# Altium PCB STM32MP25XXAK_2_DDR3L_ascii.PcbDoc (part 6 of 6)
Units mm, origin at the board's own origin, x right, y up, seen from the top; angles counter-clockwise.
Board outline 120 x 79.6 mm, 4 copper layers (Top Layer, Signal Layer 1, Signal Layer 2, Bottom Layer), stack 1.614 mm thick; 247 components, 155 nets, 1312 pads, 792 vias.
Unrouted connection lines stored in the file: 6.
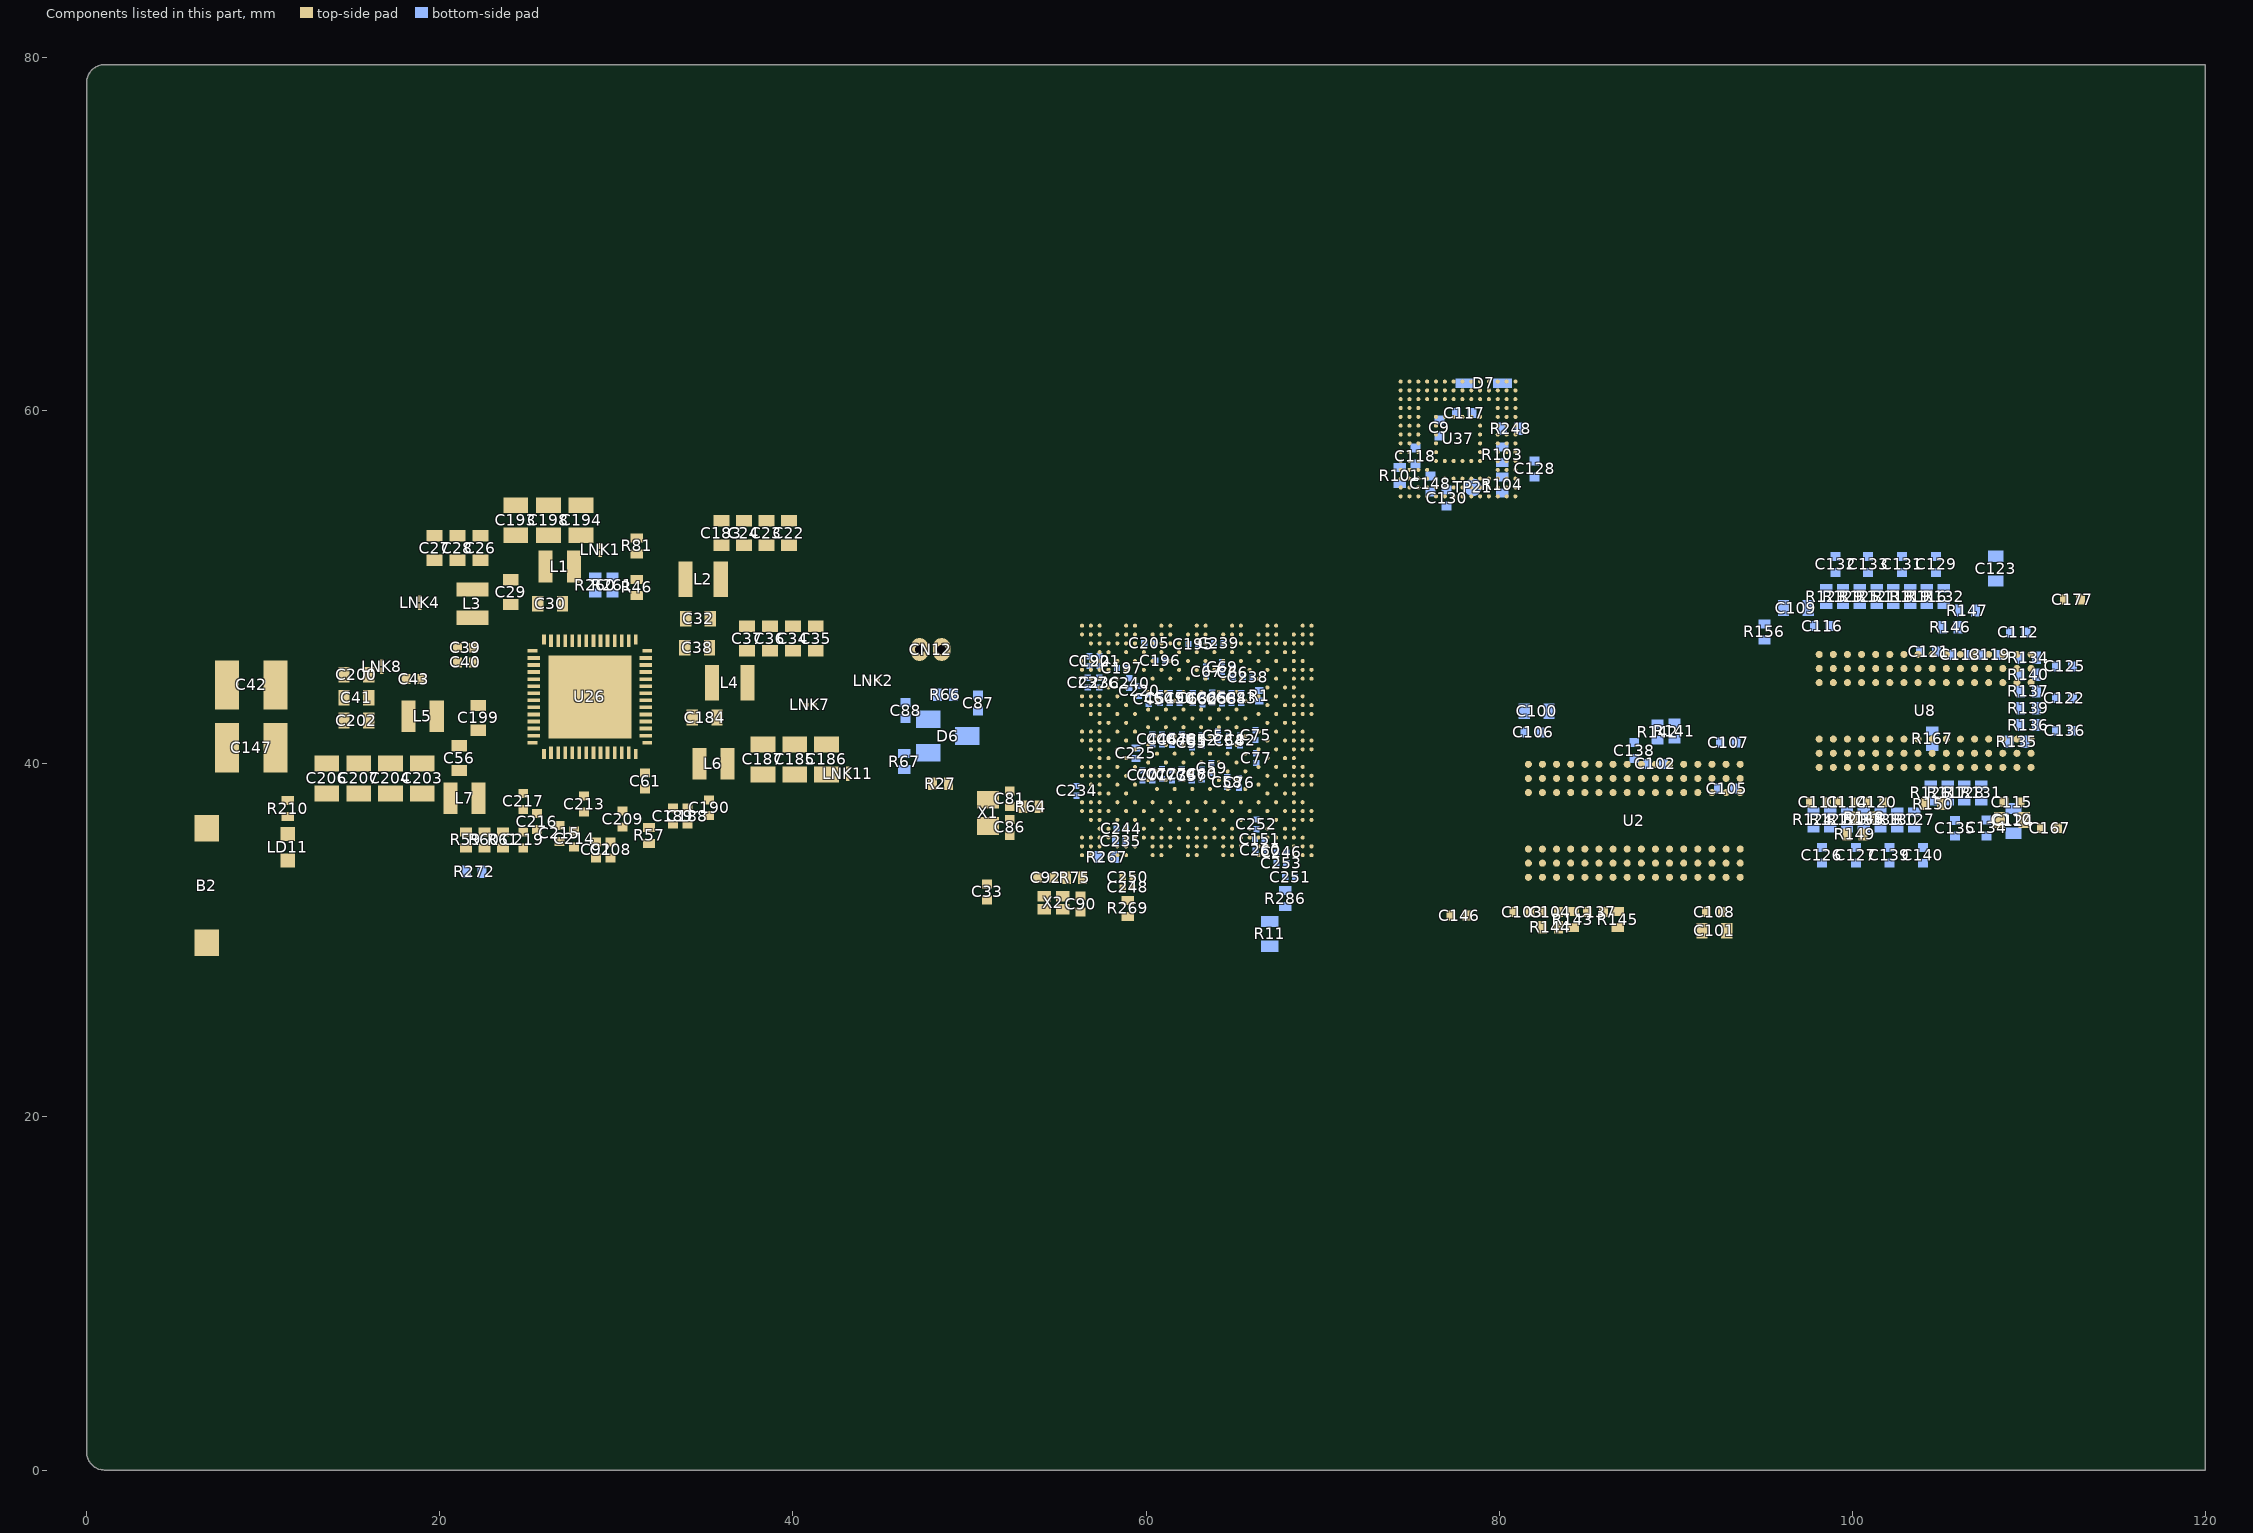
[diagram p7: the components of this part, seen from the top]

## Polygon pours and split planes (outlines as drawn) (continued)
1V8 on Signal Layer 2 "1V8_L03_P052" (solid, pour order 52): 29.175,64.6 29.175,61.472 70.193,61.472 70.252,51.21 84.26,51.21 86.225,53.175 86.225,64.6
GND on Top Layer "GND_L01_P053" (solid, remove dead copper, pour order 53): 0,79.797 119.996,79.797 119.996,0.197 0,0.197
5V_STLK on Top Layer "5V_VIN" (solid, pour order 17): 22.51,43.62 23.167,43.62 23.35,43.803 23.35,43.463 22.867,42.98 22.51,42.98
VDDCPU on Top Layer "I_SENS_VDDCPU_P" (solid, pour order 18): 17.812,51.845 17.812,49.998 18.335,49.475 22.75,49.475 22.745,49.48 22.745,51.845
VDDCORE on Top Layer "I_SENS_VDDCORE_P" (solid, pour order 19): 41.007,52.695 43.889,49.813 43.889,43.586 43.894,43.581 42.44,43.581 41.895,44.126 41.895,48.827 41.522,49.2 39.875,49.2 35.515,49.2 35.505,52.695
VDDGPU on Top Layer "I_SENS_VDDGPU_P" (solid, pour order 20): 41.603,43.6 41.745,43.742 41.745,46.72 37.025,46.72 37.025,43.6
VDDIO on Top Layer "VDDIO" (solid, pour order 22): 30.995,46.77 30.995,48.568 31.53,49.103 31.712,49.103 32.15,48.664 32.15,48.123 31.45,47.423 31.45,46.77
3V3 on Top Layer "3V3" (solid, pour order 23): 12.887,36.548 13.062,36.373 19.41,36.373 20.712,37.675 20.712,38.523 13.088,38.523 12.887,38.323
NetL6_1 on Top Layer "NetL13_1" (solid, pour order 25): 33.375,41.863 33.838,41.4 35.1,41.4 35.1,39.1 35.098,39.098 33.801,39.098 33.801,40.722 33.375,41.148
GND on Bottom Layer "GND_L04_P055" (solid, remove dead copper, pour order 55): 0,79.6 120,79.6 120,0 0,0
VTT_DDR on Bottom Layer "VTT" (solid, pour order 39): 104.31,35.002 105.908,36.6 109.033,36.6 111.658,39.225 111.658,49.075 109.583,51.15 98.183,51.15 98.183,49.627 108.079,49.627 109.983,47.724 109.983,41.223 106.96,38.2 103.996,38.2 103.996,36.702 97.158,36.702 97.158,35
GND on Signal Layer 1 "GND_L02_P000" (solid, remove dead copper, pour order 0): 0,79.6 120,79.6 120,0 0,0

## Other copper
Top Layer:
  rectangle net VDD_DDR: 15.655,41.8 18.625,43.6

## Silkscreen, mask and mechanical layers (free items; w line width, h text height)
Top Overlay:
  text "J" at 27.263,70.56 h15
Drill Drawing:
  drawing of 194 lines, arcs and shapes, not listed
  text "PCB SPECIFICATIONS :" at -27.02,127.275 h3
  text "A.   MATERIAL :" at -27.02,123.275 h3
  text "FR-4" at 11.48,123.275 h3
  text "TG-170" at 27.98,123.275 h3
  text "X  TG-150" at 46.23,123.275 h3
  text "TG-140" at 62.23,123.275 h3
  text "B.   MATERIAL FAMILY :" at -27.02,120.275 h3
  text "N/A" at 11.48,120.275 h3
  text "C.   SOLDERMASK COLOR :" at -27.02,117.275 h3
  text "GREEN" at 11.48,117.275 h3
  text "X  BLUE" at 27.98,117.275 h3
  text "RED" at 46.23,117.275 h3
  text "BLACK" at 62.23,117.275 h3
  text "D.   SILKSCREEN COLOR :" at -27.02,114.275 h3
  text "X  WHITE" at 11.48,114.275 h3
  text "YELLOW" at 27.98,114.275 h3
  text "BLACK" at 46.23,114.275 h3
  text "PCB : TYPE 4" at 187.138,113.471 h3
  text "Layer" at 122.2,111.475 h2
  text "Name" at 130.564,111.475 h2
  text "Material" at 146.732,111.475 h2
  text "Thickness" at 161.266,111.475 h2
  text "Constant" at 173.202,111.475 h2
  text "E.   SURFACE FINISH :" at -27.02,111.275 h3
  text "X  ENIG" at 11.48,111.275 h3
  text "IMMERSION SILVER" at 27.98,111.275 h3
  text "IMMERSION TIN" at 62.23,111.275 h3
  text "HASL" at 11.48,108.275 h3
  text "HASL (PB-FREE)" at 27.98,108.275 h3
  text "GOLDEN FINGER" at 62.23,108.275 h3
  text "ASPECT-RATIO, AXE Z :" at 187.138,107.971 h3
  text "Top Overlay" at 130.564,107.475 h2
  text "F.   IMPEDANCE CONTROL :" at -27.02,105.275 h3
  text "NO" at 11.48,105.275 h3
  text "X  YES" at 27.98,105.275 h3
  text "Top Solder" at 130.564,103.475 h2
  text "Solder Resist" at 146.732,103.475 h2
  text "0.025mm" at 161.266,103.475 h2
  text "3.5" at 173.202,103.475 h2
  text "G.   THROUGH VIA :" at -27.02,102.275 h3
  text "PLUG THE VIAS WHICH ARE COVERED WITH SOLDERMASK ONE OR TWO SIDE." at 11.48,102.275 h3
  text "6 :1  to  8 :1 / LEVEL \"B\"" at 187.157,101.224 h3
  text "1" at 122.2,99.475 h2
  text "Top Layer" at 130.564,99.475 h2
  text "0.037mm" at 161.266,99.475 h2
  text "PLUG MATERIAL :" at 11.48,99.275 h3
  text "X  SOLDERMASK" at 36.98,99.275 h3
  text "NON-CONDUCTIVE EPOXY." at 62.23,99.275 h3
  text "H.   STACK-UP :" at -27.02,96.275 h3
  text "SEE LAYER STACK-UP SEQUENCE FOR OVERALL THICKNESS." at 11.48,96.275 h3
  text "Dielectric 1" at 130.564,95.475 h2
  text "0.070mm" at 161.266,95.475 h2
  text "3.8" at 173.202,95.475 h2
  text "2" at 122.198,91.475 h2
  text "Signal Layer 1" at 130.564,91.475 h2
  text "0.035mm" at 161.266,91.475 h2
  text "MINIMUN PARAMETERS" at 187.25,89.695 h3
  text "Dielectric 2" at 130.564,87.475 h2
  text "1.330mm" at 161.266,87.475 h2
  text "4.3" at 173.202,87.475 h2
  text "DEFAULT" at 187.25,84.195 h3
  text "3" at 122.2,83.475 h2
  text "Signal Layer 2" at 130.564,83.475 h2
  text "0.035mm" at 161.266,83.475 h2
  text "Dielectric 3" at 130.564,79.475 h2
  text "0.070mm" at 161.266,79.475 h2
  text "3.8" at 173.202,79.475 h2
  text "TRACKS : 0.100mm           / GAPS : 0.100mm" at 187.25,78.445 h3
  text "4" at 122.2,75.475 h2
  text "Bottom Layer" at 130.564,75.475 h2
  text "0.037mm" at 161.266,75.475 h2
  text "BGA :" at 187.225,73.62 h3
  text "Bottom Solder" at 130.564,71.475 h2
  text "Solder Resist" at 146.732,71.475 h2
  text "0.025mm" at 161.266,71.475 h2
  text "3.5" at 173.202,71.475 h2
  text "TRACKS : 0.090mm           / GAPS : 0.090mm" at 187.225,67.87 h3
  text "Bottom Overlay" at 130.564,67.475 h2
  text "Symbol" at 108.265,-10.258 h2.4
  text "Count" at 117.653,-10.258 h2.4
  text "Hole Size" at 127.378,-10.258 h2.4
  text "Plated" at 138.78,-10.258 h2.4
  text "Hole Type" at 147.023,-10.258 h2.4
  text "Drill Layer Pair" at 159.023,-10.258 h2.4
  text "Via/Pad" at 181.752,-10.258 h2.4
  text "Pad Shape" at 191.584,-10.258 h2.4
  text "Hole Length" at 204.429,-10.258 h2.4
  text "392" at 117.653,-14.395 h2
  text "0.200mm" at 127.378,-14.395 h2
  text "PTH" at 138.78,-14.395 h2
  text "Round" at 147.023,-14.395 h2
  text "Top Layer - Bottom Layer" at 159.023,-14.395 h2
  text "Via" at 181.752,-14.395 h2
  text "Rounded" at 191.584,-14.395 h2
  text "-" at 204.429,-14.395 h2
  text "D" at 107.477,-14.649 h1.84
  text "125" at 117.653,-18.533 h2
  text "0.250mm" at 127.378,-18.533 h2
  text "PTH" at 138.78,-18.533 h2
  text "Round" at 147.023,-18.533 h2
  text "Top Layer - Bottom Layer" at 159.023,-18.533 h2
  text "Via" at 181.752,-18.533 h2
  text "Rounded" at 191.584,-18.533 h2
  text "-" at 204.429,-18.533 h2
  text "275" at 117.653,-22.67 h2
  text "0.350mm" at 127.378,-22.67 h2
  text "PTH" at 138.78,-22.67 h2
  text "Round" at 147.023,-22.67 h2
  text "Top Layer - Bottom Layer" at 159.023,-22.67 h2
  text "Via" at 181.752,-22.67 h2
  text "Rounded" at 191.584,-22.67 h2
  text "-" at 204.429,-22.67 h2
  text "C" at 107.477,-22.924 h1.84
  text "2" at 117.653,-26.807 h2
  text "0.500mm" at 127.378,-26.807 h2
  text "PTH" at 138.78,-26.807 h2
  text "Round" at 147.023,-26.807 h2
  text "Top Layer - Bottom Layer" at 159.023,-26.807 h2
  text "Pad" at 181.752,-26.807 h2
  text "Rounded" at 191.584,-26.807 h2
  text "-" at 204.429,-26.807 h2
  text "794 Total" at 117.653,-30.945 h2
